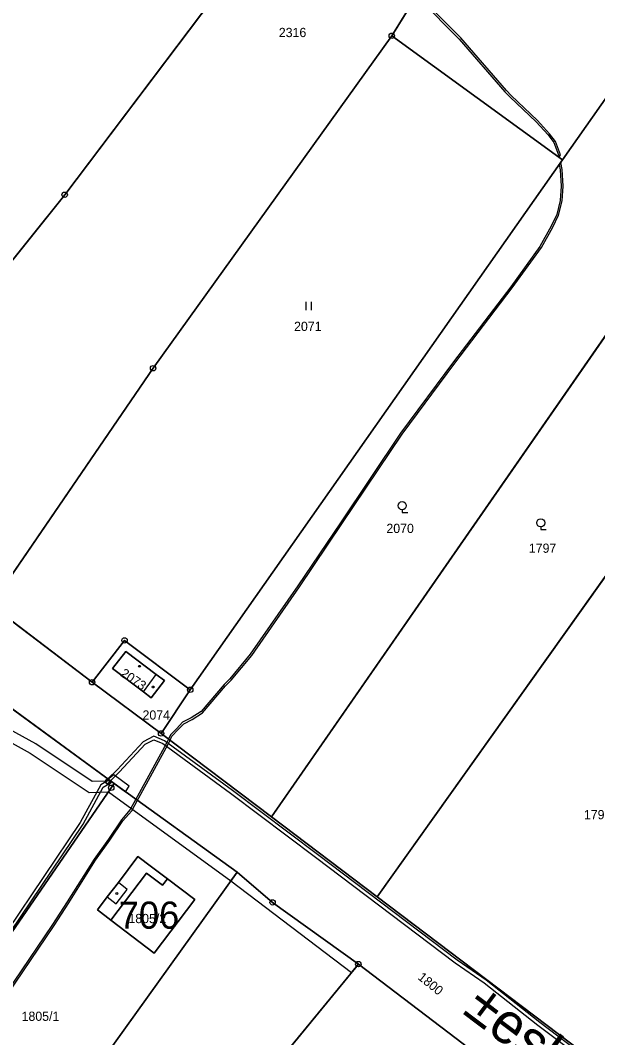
# Model space of a CAD drawing. Extents: x -689422 to -685210, y -987725 to -982160.
# Drawn here: x -687651.6 to -687545.1, y -985080 to -984892.5 of the extents above; entities that cross this region are included whole.
import ezdxf

# ---------------------------------------------------------------- set-up
doc = ezdxf.new("R2010")
doc.units = 0
for name, color, linetype in [('KN_Budovy', 7, 'Continuous'), ('KN_Budovy_cisla_domovni', 7, 'Continuous'), ('KN_Hranice_parcel', 7, 'Continuous'), ('KN_Hranice_parcel_vnitrni_kresba', 7, 'Continuous'), ('KN_Parcelni cisla', 7, 'Continuous'), ('KN_Polygon parcely', 7, 'Continuous'), ('KN_Popisy_pomistni nazvy nazvy ulic', 7, 'Continuous'), ('KN_POZEMKY_ORNA PUDA', 7, 'Continuous'), ('KN_POZEMKY_OSTATNI PLOCHA', 7, 'Continuous'), ('KN_POZEMKY_OVOCNY_SAD', 7, 'Continuous'), ('KN_POZEMKY_TTP', 7, 'Continuous'), ('KN_POZEMKY_ZAHRADA', 7, 'Continuous'), ('KN_POZEMKY_ZASTAVENA PLOCHA', 7, 'Continuous'), ('KN_VYUZITI_16_ostatni plocha_silnice', 7, 'Continuous'), ('KN_VYUZITI_23_ostatni plocha_manipulacni plocha', 7, 'Continuous'), ('KN_Věcná břemena k části', 7, 'Continuous'), ('KN_Značky bodu BP', 7, 'Continuous'), ('KN_Značky budov', 7, 'Continuous'), ('KN_Značky kultur', 7, 'Continuous')]:
    doc.layers.add(name, color=color, linetype=linetype)

msp = doc.modelspace()

# ---------------------------------------------------------------- linework, layer by layer
at = {"layer": 'KN_Budovy'}
for points in [[(-687634.55, -985011.94), (-687628.87, -985016.26), (-687626.51, -985013.04), (-687632.13, -985008.8)], [(-687626.89, -985064.38), (-687619.39, -985054.5), (-687624.46, -985050.72), (-687625.37, -985051.86), (-687628.29, -985049.67), (-687634.9, -985058.33)]]:
    msp.add_lwpolyline(points, close=True, dxfattribs=at)
at = {"layer": 'KN_Hranice_parcel'}
for p, q in [((-687551.59, -984918.2), (-687583.1, -984895.36)), ((-687551.59, -984918.2), (-687620.25, -985015.87)), ((-687526.81, -984926.28), (-687605.26, -985039.31)), ((-687638.33, -985014.48), (-687656.99, -985000.3)), ((-687676.7, -985002.14), (-687634.28, -985033.15)), ((-687625.62, -985023.92), (-687638.33, -985014.48)), ((-687620.25, -985015.87), (-687625.62, -985023.92)), ((-687605.26, -985039.31), (-687625.62, -985023.92)), ((-687634.28, -985033.15), (-687611.58, -985049.47)), ((-687605.26, -985039.31), (-687585.79, -985054.04)), ((-687611.58, -985049.47), (-687648.4, -985100.74)), ((-687547.85, -985082.73), (-687585.79, -985054.04)), ((-687627.5, -985112.99), (-687589.25, -985066.42))]:
    msp.add_line(p, q, dxfattribs=at)
for points in [[(-687583.1, -984895.36), (-687562.57, -984862.29), (-687550.97, -984829.93), (-687533.16, -984761.41)], [(-687686.61, -984978.67), (-687643.39, -984924.65), (-687599.51, -984866.59)], [(-687528.89, -984894.98), (-687541.72, -984904.16), (-687551.59, -984918.2)], [(-687583.1, -984895.36), (-687627.09, -984956.62), (-687656.99, -985000.3)], [(-687585.79, -985054.04), (-687535.53, -984983.48), (-687520.73, -984964.06)], [(-687638.33, -985014.48), (-687632.36, -985006.77), (-687620.25, -985015.87)], [(-687628.87, -985016.26), (-687627.45, -985017.34), (-687624.99, -985014.19), (-687626.51, -985013.04), (-687632.13, -985008.8), (-687634.55, -985011.94), (-687628.87, -985016.26)], [(-687653.89, -985061.65), (-687634.82, -985033.93), (-687634.28, -985033.15)], [(-687634.9, -985058.33), (-687637.37, -985056.45), (-687635.54, -985054.05), (-687633.48, -985051.37), (-687629.91, -985046.59), (-687627.41, -985048.52), (-687624.46, -985050.72), (-687619.39, -985054.5), (-687626.89, -985064.38), (-687634.9, -985058.33)], [(-687611.58, -985049.47), (-687605.06, -985055.05), (-687589.25, -985066.42)], [(-687589.25, -985066.42), (-687569.9, -985081.12), (-687567.88, -985082.71)]]:
    msp.add_lwpolyline(points, dxfattribs=at)
at = {"layer": 'KN_Hranice_parcel_vnitrni_kresba'}
for p, q in [((-687628.87, -985016.26), (-687626.51, -985013.04)), ((-687633.88, -985055.34), (-687631.85, -985052.65)), ((-687631.85, -985052.65), (-687633.48, -985051.37)), ((-687635.54, -985054.05), (-687633.88, -985055.34))]:
    msp.add_line(p, q, dxfattribs=at)
msp.add_lwpolyline([(-687634.9, -985058.33), (-687628.29, -985049.67), (-687625.37, -985051.86), (-687624.46, -985050.72)], dxfattribs=at)
at = {"layer": 'KN_Polygon parcely'}
for points in [[(-687524.37, -984718.56), (-687513.26, -984643.33), (-687516.05, -984642.24), (-687526.38, -984637.98), (-687539.51, -984739.56), (-687556.05, -984788.06), (-687586.58, -984850.42), (-687599.51, -984866.59), (-687643.39, -984924.65), (-687686.61, -984978.67), (-687656.99, -985000.3), (-687627.09, -984956.62), (-687583.1, -984895.36), (-687562.57, -984862.29), (-687550.97, -984829.93), (-687533.16, -984761.41)], [(-687684.33, -984835.4), (-687696.16, -984852.64), (-687708.13, -984876.25), (-687748.07, -984933.14), (-687748.45, -984933.68), (-687731.63, -984947.48), (-687686.61, -984978.67), (-687643.39, -984924.65), (-687599.51, -984866.59), (-687612.12, -984862.95), (-687603, -984835.9), (-687610.04, -984839.45), (-687630.08, -984840.21), (-687635.61, -984835.53), (-687669.54, -984834.16)], [(-687625.62, -985023.92), (-687605.26, -985039.31), (-687526.81, -984926.28), (-687528.89, -984894.98), (-687541.72, -984904.16), (-687551.59, -984918.2), (-687620.25, -985015.87)], [(-687627.09, -984956.62), (-687656.99, -985000.3), (-687638.33, -985014.48), (-687632.36, -985006.77), (-687620.25, -985015.87), (-687551.59, -984918.2), (-687583.1, -984895.36)], [(-687585.79, -985054.04), (-687535.53, -984983.48), (-687520.73, -984964.06), (-687522.14, -984959.78), (-687525.16, -984951.03), (-687526.81, -984926.28), (-687605.26, -985039.31)], [(-687679.93, -985039.52), (-687675.09, -985043.63), (-687653.89, -985061.65), (-687634.82, -985033.93), (-687634.28, -985033.15), (-687676.7, -985002.14), (-687693.14, -985030.09)], [(-687638.33, -985014.48), (-687625.62, -985023.92), (-687620.25, -985015.87), (-687632.36, -985006.77)], [(-687628.87, -985016.26), (-687627.45, -985017.34), (-687624.99, -985014.19), (-687626.51, -985013.04), (-687632.13, -985008.8), (-687634.55, -985011.94)], [(-687628.87, -985016.26), (-687634.55, -985011.94), (-687632.13, -985008.8), (-687626.51, -985013.04), (-687624.99, -985014.19), (-687627.45, -985017.34)], [(-687611.58, -985049.47), (-687634.28, -985033.15), (-687634.82, -985033.93), (-687653.89, -985061.65), (-687655, -985063.32), (-687655.59, -985064.2), (-687668.87, -985090.37), (-687648.4, -985100.74)], [(-687634.9, -985058.33), (-687637.37, -985056.45), (-687635.54, -985054.05), (-687633.48, -985051.37), (-687629.91, -985046.59), (-687627.41, -985048.52), (-687624.46, -985050.72), (-687619.39, -985054.5), (-687626.89, -985064.38)], [(-687634.9, -985058.33), (-687626.89, -985064.38), (-687619.39, -985054.5), (-687624.46, -985050.72), (-687627.41, -985048.52), (-687629.91, -985046.59), (-687633.48, -985051.37), (-687635.54, -985054.05), (-687637.37, -985056.45)], [(-687627.5, -985112.99), (-687589.25, -985066.42), (-687605.06, -985055.05), (-687611.58, -985049.47), (-687648.4, -985100.74)], [(-687567.88, -985082.71), (-687569.9, -985081.12), (-687589.25, -985066.42), (-687627.5, -985112.99), (-687603.25, -985125.69)]]:
    msp.add_lwpolyline(points, close=True, dxfattribs=at)
for points in [[(-687533.16, -984761.41), (-687550.97, -984829.93), (-687562.57, -984862.29), (-687583.1, -984895.36), (-687551.59, -984918.2), (-687541.72, -984904.16)], [(-687804.21, -984883.79), (-687794.59, -984897.73), (-687784.13, -984912.02), (-687779.78, -984917.32), (-687755.71, -984944.63), (-687751.7, -984947.54), (-687728.9, -984964.08), (-687696.81, -984987.44), (-687676.7, -985002.14), (-687634.28, -985033.15), (-687611.58, -985049.47), (-687605.06, -985055.05), (-687589.25, -985066.42), (-687569.9, -985081.12), (-687567.88, -985082.71), (-687545.22, -985101.04), (-687533.51, -985110)], [(-687530.18, -985097.82), (-687547.85, -985082.73), (-687585.79, -985054.04), (-687605.26, -985039.31), (-687625.62, -985023.92), (-687638.33, -985014.48), (-687656.99, -985000.3), (-687686.61, -984978.67), (-687731.63, -984947.48), (-687748.45, -984933.68), (-687764.19, -984917.52), (-687771.32, -984908.97), (-687778.07, -984899.31), (-687785.83, -984887.43)], [(-687535.53, -984983.48), (-687585.79, -985054.04), (-687547.85, -985082.73), (-687530.18, -985097.82)]]:
    msp.add_lwpolyline(points, dxfattribs=at)
at = {"layer": 'KN_POZEMKY_ORNA PUDA'}
for p, q in [((-687634.82, -985033.93), (-687634.28, -985033.15)), ((-687634.28, -985033.15), (-687611.58, -985049.47)), ((-687653.89, -985061.65), (-687634.82, -985033.93)), ((-687629.91, -985046.59), (-687633.48, -985051.37)), ((-687627.41, -985048.52), (-687629.91, -985046.59)), ((-687624.46, -985050.72), (-687627.41, -985048.52)), ((-687611.58, -985049.47), (-687648.4, -985100.74)), ((-687648.4, -985100.74), (-687611.58, -985049.47)), ((-687619.39, -985054.5), (-687624.46, -985050.72)), ((-687611.58, -985049.47), (-687605.06, -985055.05)), ((-687633.48, -985051.37), (-687635.54, -985054.05)), ((-687635.54, -985054.05), (-687637.37, -985056.45)), ((-687626.89, -985064.38), (-687619.39, -985054.5)), ((-687605.06, -985055.05), (-687589.25, -985066.42)), ((-687637.37, -985056.45), (-687634.9, -985058.33)), ((-687634.9, -985058.33), (-687626.89, -985064.38)), ((-687589.25, -985066.42), (-687627.5, -985112.99))]:
    msp.add_line(p, q, dxfattribs=at)
at = {"layer": 'KN_POZEMKY_OSTATNI PLOCHA'}
for p, q in [((-687656.99, -985000.3), (-687638.33, -985014.48)), ((-687634.28, -985033.15), (-687676.7, -985002.14)), ((-687638.33, -985014.48), (-687632.36, -985006.77)), ((-687632.36, -985006.77), (-687620.25, -985015.87)), ((-687632.13, -985008.8), (-687634.55, -985011.94)), ((-687626.51, -985013.04), (-687632.13, -985008.8)), ((-687634.55, -985011.94), (-687628.87, -985016.26)), ((-687624.99, -985014.19), (-687626.51, -985013.04)), ((-687625.62, -985023.92), (-687638.33, -985014.48)), ((-687638.33, -985014.48), (-687625.62, -985023.92)), ((-687627.45, -985017.34), (-687624.99, -985014.19)), ((-687628.87, -985016.26), (-687627.45, -985017.34)), ((-687620.25, -985015.87), (-687625.62, -985023.92)), ((-687625.62, -985023.92), (-687605.26, -985039.31)), ((-687611.58, -985049.47), (-687634.28, -985033.15)), ((-687605.26, -985039.31), (-687585.79, -985054.04)), ((-687605.06, -985055.05), (-687611.58, -985049.47)), ((-687585.79, -985054.04), (-687547.85, -985082.73)), ((-687589.25, -985066.42), (-687605.06, -985055.05)), ((-687569.9, -985081.12), (-687589.25, -985066.42))]:
    msp.add_line(p, q, dxfattribs=at)
at = {"layer": 'KN_POZEMKY_OVOCNY_SAD'}
for p, q in [((-687551.59, -984918.2), (-687541.72, -984904.16)), ((-687620.25, -985015.87), (-687551.59, -984918.2)), ((-687605.26, -985039.31), (-687526.81, -984926.28)), ((-687526.81, -984926.28), (-687605.26, -985039.31)), ((-687535.53, -984983.48), (-687585.79, -985054.04)), ((-687625.62, -985023.92), (-687620.25, -985015.87)), ((-687605.26, -985039.31), (-687625.62, -985023.92)), ((-687585.79, -985054.04), (-687605.26, -985039.31))]:
    msp.add_line(p, q, dxfattribs=at)
at = {"layer": 'KN_POZEMKY_TTP'}
for p, q in [((-687583.1, -984895.36), (-687562.57, -984862.29)), ((-687562.57, -984862.29), (-687583.1, -984895.36)), ((-687599.51, -984866.59), (-687643.39, -984924.65)), ((-687643.39, -984924.65), (-687599.51, -984866.59)), ((-687583.1, -984895.36), (-687627.09, -984956.62)), ((-687627.09, -984956.62), (-687583.1, -984895.36)), ((-687551.59, -984918.2), (-687583.1, -984895.36)), ((-687583.1, -984895.36), (-687551.59, -984918.2)), ((-687541.72, -984904.16), (-687551.59, -984918.2)), ((-687551.59, -984918.2), (-687620.25, -985015.87)), ((-687643.39, -984924.65), (-687686.61, -984978.67)), ((-687686.61, -984978.67), (-687643.39, -984924.65)), ((-687627.09, -984956.62), (-687656.99, -985000.3)), ((-687656.99, -985000.3), (-687627.09, -984956.62)), ((-687585.79, -985054.04), (-687535.53, -984983.48)), ((-687638.33, -985014.48), (-687656.99, -985000.3)), ((-687632.36, -985006.77), (-687638.33, -985014.48)), ((-687620.25, -985015.87), (-687632.36, -985006.77)), ((-687547.85, -985082.73), (-687585.79, -985054.04))]:
    msp.add_line(p, q, dxfattribs=at)
at = {"layer": 'KN_POZEMKY_ZAHRADA'}
for p, q in [((-687676.7, -985002.14), (-687634.28, -985033.15)), ((-687634.28, -985033.15), (-687634.82, -985033.93)), ((-687634.82, -985033.93), (-687653.89, -985061.65)), ((-687627.5, -985112.99), (-687589.25, -985066.42)), ((-687589.25, -985066.42), (-687569.9, -985081.12))]:
    msp.add_line(p, q, dxfattribs=at)
at = {"layer": 'KN_POZEMKY_ZASTAVENA PLOCHA'}
for p, q in [((-687634.55, -985011.94), (-687632.13, -985008.8)), ((-687632.13, -985008.8), (-687626.51, -985013.04)), ((-687628.87, -985016.26), (-687634.55, -985011.94)), ((-687626.51, -985013.04), (-687624.99, -985014.19)), ((-687624.99, -985014.19), (-687627.45, -985017.34)), ((-687627.45, -985017.34), (-687628.87, -985016.26)), ((-687633.48, -985051.37), (-687629.91, -985046.59)), ((-687629.91, -985046.59), (-687627.41, -985048.52)), ((-687627.41, -985048.52), (-687624.46, -985050.72)), ((-687624.46, -985050.72), (-687619.39, -985054.5)), ((-687635.54, -985054.05), (-687633.48, -985051.37)), ((-687637.37, -985056.45), (-687635.54, -985054.05)), ((-687619.39, -985054.5), (-687626.89, -985064.38)), ((-687634.9, -985058.33), (-687637.37, -985056.45)), ((-687626.89, -985064.38), (-687634.9, -985058.33))]:
    msp.add_line(p, q, dxfattribs=at)
at = {"layer": 'KN_VYUZITI_16_ostatni plocha_silnice'}
for p, q in [((-687656.99, -985000.3), (-687638.33, -985014.48)), ((-687634.28, -985033.15), (-687676.7, -985002.14)), ((-687638.33, -985014.48), (-687625.62, -985023.92)), ((-687625.62, -985023.92), (-687605.26, -985039.31)), ((-687611.58, -985049.47), (-687634.28, -985033.15)), ((-687605.26, -985039.31), (-687585.79, -985054.04)), ((-687605.06, -985055.05), (-687611.58, -985049.47)), ((-687585.79, -985054.04), (-687547.85, -985082.73)), ((-687589.25, -985066.42), (-687605.06, -985055.05)), ((-687569.9, -985081.12), (-687589.25, -985066.42))]:
    msp.add_line(p, q, dxfattribs=at)
at = {"layer": 'KN_VYUZITI_23_ostatni plocha_manipulacni plocha'}
for p, q in [((-687638.33, -985014.48), (-687632.36, -985006.77)), ((-687632.36, -985006.77), (-687620.25, -985015.87)), ((-687632.13, -985008.8), (-687634.55, -985011.94)), ((-687626.51, -985013.04), (-687632.13, -985008.8)), ((-687634.55, -985011.94), (-687628.87, -985016.26)), ((-687624.99, -985014.19), (-687626.51, -985013.04)), ((-687625.62, -985023.92), (-687638.33, -985014.48)), ((-687627.45, -985017.34), (-687624.99, -985014.19)), ((-687628.87, -985016.26), (-687627.45, -985017.34)), ((-687620.25, -985015.87), (-687625.62, -985023.92))]:
    msp.add_line(p, q, dxfattribs=at)
at = {"layer": 'KN_Věcná břemena k části'}
for points in [[(-687552.91, -984914.87), (-687553.99, -984913.42), (-687556.25, -984910.97), (-687561.08, -984906.38), (-687561.96, -984905.45), (-687570.38, -984895.72), (-687577.71, -984888.31), (-687578.33, -984887.68), (-687578.52, -984887.99), (-687577.91, -984888.61), (-687570.64, -984895.96), (-687562.22, -984905.68), (-687561.33, -984906.63), (-687556.5, -984911.21), (-687554.26, -984913.64), (-687553.22, -984915.04), (-687552.35, -984917.31), (-687552.52, -984917.52), (-687552.11, -984917.82), (-687552.15, -984917.61), (-687552, -984917.32)], [(-687552.05, -984920.06), (-687551.86, -984923.06), (-687552.04, -984925.72), (-687552.66, -984928.31), (-687553.7, -984930.46), (-687555.78, -984934.2), (-687561.17, -984941.59), (-687571.73, -984955.45), (-687581.46, -984968.57), (-687592.57, -984985.12), (-687600.42, -984996.74), (-687609.17, -985009.33), (-687612.96, -985013.84), (-687613.99, -985014.92), (-687618.2, -985019.86), (-687620.05, -985021.05), (-687621.66, -985021.87), (-687622.73, -985022.98), (-687623.89, -985024.18), (-687624.24, -985024.96), (-687623.97, -985025.17), (-687623.64, -985024.42), (-687622.45, -985023.19), (-687621.45, -985022.15), (-687619.87, -985021.35), (-687617.97, -985020.13), (-687613.73, -985015.16), (-687612.7, -985014.07), (-687608.89, -985009.55), (-687600.13, -984996.93), (-687592.28, -984985.32), (-687581.18, -984968.77), (-687571.45, -984955.66), (-687560.89, -984941.8), (-687555.48, -984934.39), (-687553.39, -984930.62), (-687552.33, -984928.43), (-687551.7, -984925.77), (-687551.51, -984923.06), (-687551.7, -984920.01), (-687551.95, -984918.71), (-687552.22, -984919.1)], [(-687635.82, -985032.7), (-687638.32, -985032.78), (-687648.71, -985025.85), (-687659.14, -985020.09), (-687679.04, -985006.11), (-687680.05, -985007.84), (-687660.2, -985021.79), (-687649.75, -985027.57), (-687638.9, -985034.8), (-687635.34, -985034.69), (-687634.82, -985033.93), (-687634.28, -985033.15), (-687635.37, -985032.35)], [(-687630.03, -985035.6), (-687630.27, -985036.03), (-687629.98, -985036.24), (-687629.75, -985035.81), (-687624.29, -985025.89), (-687623.97, -985025.17), (-687624.24, -985024.96), (-687624.6, -985025.74)], [(-687632.19, -985034.65), (-687631.5, -985033.63), (-687634.36, -985031.57), (-687635.37, -985032.35), (-687634.28, -985033.15)], [(-687653.92, -985060.24), (-687654.56, -985061.08), (-687654.1, -985061.47), (-687653.44, -985060.58), (-687639.99, -985040.63), (-687636.29, -985033.82), (-687634.82, -985032.96), (-687635.35, -985032.58), (-687636.73, -985033.38), (-687640.51, -985040.31)], [(-687635.02, -985033.08), (-687635.26, -985032.92), (-687634.97, -985032.64), (-687635.46, -985032.28), (-687635.81, -985032.53), (-687636.01, -985032.8), (-687635.25, -985033.37)], [(-687634.97, -985032.64), (-687635.46, -985032.28), (-687635.93, -985032.9), (-687635.45, -985033.27)], [(-687612.75, -985051.09), (-687611.58, -985049.47), (-687634.28, -985033.15), (-687634.82, -985033.93), (-687635.34, -985034.69)], [(-687612.75, -985051.09), (-687590.52, -985067.97), (-687589.25, -985066.42), (-687605.06, -985055.05), (-687611.58, -985049.47)]]:
    msp.add_lwpolyline(points, close=True, dxfattribs=at)
for points in [[(-687542.34, -985087.43), (-687547.36, -985083.55), (-687555.82, -985077.18), (-687565.72, -985069.41), (-687571.04, -985065.68), (-687596.81, -985046.24), (-687612.46, -985034.46), (-687625, -985025.27), (-687626.96, -985024.43), (-687628.92, -985025.44), (-687633.7, -985030.6), (-687635.46, -985032.28), (-687634.97, -985032.64), (-687633.28, -985031.02), (-687628.56, -985025.92), (-687626.94, -985025.09), (-687625.3, -985025.79), (-687612.82, -985034.94), (-687597.17, -985046.72), (-687571.4, -985066.16), (-687566.08, -985069.89), (-687556.18, -985077.66), (-687547.72, -985084.03), (-687542.45, -985087.9)], [(-687659.04, -985080.18), (-687653.91, -985072.05), (-687645.33, -985059.3), (-687642.63, -985055.11), (-687637.69, -985047.27), (-687635.06, -985043.57), (-687632.65, -985040.05), (-687631.04, -985038.16), (-687629.98, -985036.24), (-687630.27, -985036.03), (-687631.33, -985037.96), (-687632.92, -985039.84), (-687635.34, -985043.37), (-687637.98, -985047.08), (-687642.93, -985054.92), (-687645.62, -985059.11), (-687654.21, -985071.86), (-687659.34, -985080)]]:
    msp.add_lwpolyline(points, dxfattribs=at)
at = {"layer": 'KN_Značky bodu BP'}
for centre, radius in [((-687583.1, -984895.36), 0.5), ((-687583.1, -984895.36), 0.0303), ((-687643.39, -984924.65), 0.5), ((-687643.39, -984924.65), 0.0303), ((-687627.09, -984956.62), 0.5), ((-687627.09, -984956.62), 0.0303), ((-687632.36, -985006.77), 0.5), ((-687632.36, -985006.77), 0.0303), ((-687638.33, -985014.48), 0.5), ((-687638.33, -985014.48), 0.0303), ((-687620.25, -985015.87), 0.5), ((-687620.25, -985015.87), 0.0303), ((-687625.62, -985023.92), 0.5), ((-687625.62, -985023.92), 0.0303), ((-687634.82, -985033.93), 0.5), ((-687634.82, -985033.93), 0.0303), ((-687605.06, -985055.05), 0.5), ((-687605.06, -985055.05), 0.0303), ((-687589.25, -985066.42), 0.5), ((-687589.25, -985066.42), 0.0303)]:
    msp.add_circle(centre, radius, dxfattribs=at)
at = {"layer": 'KN_Značky budov'}
for centre in [(-687629.59, -985011.55), (-687627.07, -985015.36), (-687633.79, -985053.42), (-687627.76, -985055.13)]:
    msp.add_circle(centre, 0.175, dxfattribs=at)
at = {"layer": 'KN_Značky kultur'}
for p, q in [((-687598.9, -984945.9), (-687598.9, -984944.4)), ((-687597.9, -984945.9), (-687597.9, -984944.4)), ((-687581.16, -984982.7), (-687581.16, -984983.2)), ((-687581.16, -984983.2), (-687580.16, -984983.2)), ((-687555.62, -984985.86), (-687555.62, -984986.36)), ((-687555.62, -984986.36), (-687554.62, -984986.36))]:
    msp.add_line(p, q, dxfattribs=at)
for centre in [(-687581.16, -984981.95), (-687555.62, -984985.11)]:
    msp.add_circle(centre, 0.75, dxfattribs=at)

# ---------------------------------------------------------------- texts
at = {"layer": 'KN_Budovy_cisla_domovni'}
msp.add_text('706', height=5, dxfattribs=at).set_placement((-687633.43, -985059.9))
at = {"layer": 'KN_Parcelni cisla'}
for s, p in [('2316', (-687603.91, -984895.6)), ('2071', (-687601.1, -984949.75)), ('2070', (-687584.08, -984986.98)), ('1797', (-687557.82, -984990.63)), ('2074', (-687629.04, -985021.37)), ('1790/3', (-687547.67, -985039.73)), ('1805/2', (-687631.64, -985058.87)), ('1805/1', (-687651.33, -985076.88))]:
    msp.add_text(s, height=1.7, dxfattribs=at).set_placement(p)
for s, rotation, p in [('2073', 326, (-687633.28, -985013.22)), ('1800', 321, (-687578.42, -985069.09))]:
    msp.add_text(s, height=1.7, rotation=rotation, dxfattribs=at).set_placement(p)
at = {"layer": 'KN_Popisy_pomistni nazvy nazvy ulic'}
msp.add_text('±eskodubská', height=7.5, rotation=323, dxfattribs=at).set_placement((-687570.19, -985075.43))

doc.saveas('drawing.dxf')
